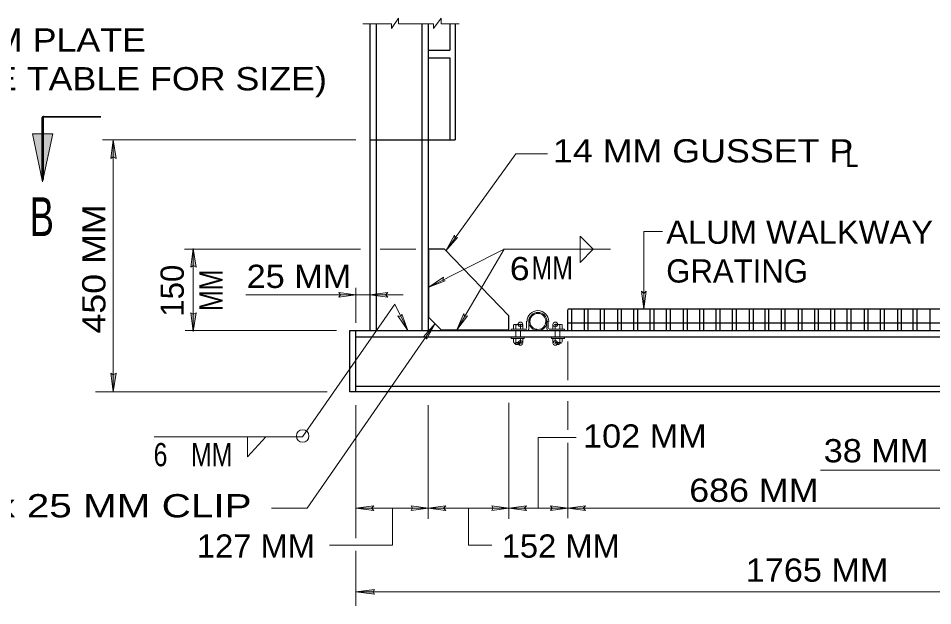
# Model space of a CAD drawing. Extents: x 312601.858 to 312602.699, y 144420.109 to 144420.704.
# Drawn here: x 312601.9235 to 312602.0414, y 144420.4587 to 144420.5345 of the extents above; entities that cross this region are included whole.
import ezdxf
from ezdxf.enums import TextEntityAlignment as Align

# ---------------------------------------------------------------- set-up
doc = ezdxf.new("R2010")
doc.units = 0
doc.header["$LTSCALE"] = 0.0012
doc.header["$PDMODE"] = 32
doc.header["$PDSIZE"] = 0.0006
doc.linetypes.add('LONG_DASHED', pattern=[7.5, 6, -1.5])
for name, color, linetype, lineweight in [('1', 7, 'Continuous', 13), ('2', 7, 'Continuous', 13), ('3', 7, 'Continuous', 13), ('39', 7, 'Continuous', 13), ('5', 7, 'Continuous', 25)]:
    doc.layers.add(name, color=color, linetype=linetype, lineweight=lineweight)

msp = doc.modelspace()

# ---------------------------------------------------------------- hatches: boundary and pattern name
at = {"layer": '1'}
for points in [[(312601.9253, 144420.5196), (312601.9266, 144420.5196), (312601.9266, 144420.5134)], [(312601.9253, 144420.5196), (312601.9266, 144420.5196), (312601.9266, 144420.5134)], [(312601.9279, 144420.5196), (312601.9266, 144420.5196), (312601.9266, 144420.5134)], [(312601.9279, 144420.5196), (312601.9266, 144420.5196), (312601.9266, 144420.5134)]]:
    msp.add_hatch(color=256, dxfattribs=at).paths.add_polyline_path(points)
at = {"layer": '39'}
for points in [[(312601.9357, 144420.5166), (312601.9354, 144420.5164), (312601.9357, 144420.5188), (312601.9361, 144420.5164)], [(312601.946, 144420.5026), (312601.9457, 144420.5024), (312601.946, 144420.5048), (312601.9464, 144420.5024)], [(312601.946, 144420.4963), (312601.9464, 144420.4965), (312601.946, 144420.4941), (312601.9457, 144420.4965)], [(312601.9357, 144420.4885), (312601.9361, 144420.4887), (312601.9357, 144420.4863), (312601.9354, 144420.4887)], [(312601.9692, 144420.4605), (312601.9694, 144420.4602), (312601.967, 144420.4605), (312601.9694, 144420.4608)], [(312601.9692, 144420.4605), (312601.9694, 144420.4602), (312601.967, 144420.4605), (312601.9694, 144420.4608)]]:
    msp.add_hatch(color=256, dxfattribs=at).paths.add_polyline_path(points)

# ---------------------------------------------------------------- linework, layer by layer
at = {"layer": '1'}
for p, q in [((312601.9679, 144420.5338), (312601.9716, 144420.5338)), ((312601.9716, 144420.5332), (312601.9725, 144420.5345)), ((312601.9716, 144420.5332), (312601.9716, 144420.5338)), ((312601.9725, 144420.5338), (312601.9725, 144420.5345)), ((312601.9725, 144420.5338), (312601.977, 144420.5338)), ((312601.977, 144420.5332), (312601.978, 144420.5345)), ((312601.977, 144420.5332), (312601.977, 144420.5338)), ((312601.978, 144420.5338), (312601.978, 144420.5345)), ((312601.978, 144420.5338), (312601.9803, 144420.5338)), ((312601.9265, 144420.5137), (312601.9265, 144420.5217)), ((312601.9343, 144420.5188), (312601.967, 144420.5188)), ((312601.9357, 144420.5188), (312601.9357, 144420.4863)), ((312602.0041, 144420.497), (312602.0041, 144420.507)), ((312602.0041, 144420.507), (312602.0065, 144420.507)), ((312601.9959, 144420.5064), (312601.9976, 144420.5047)), ((312601.9676, 144420.5047), (312601.9449, 144420.5047)), ((312601.946, 144420.5047), (312601.946, 144420.4942)), ((312601.9747, 144420.5047), (312601.9701, 144420.5047)), ((312601.9764, 144420.4998), (312601.9861, 144420.5047)), ((312601.9764, 144420.5047), (312601.9764, 144420.4959)), ((312601.98, 144420.4943), (312601.9861, 144420.5047)), ((312601.986, 144420.5047), (312601.9998, 144420.5047)), ((312601.9959, 144420.503), (312601.9976, 144420.5047)), ((312601.967, 144420.4952), (312601.967, 144420.4997)), ((312601.967, 144420.4988), (312601.9528, 144420.4988)), ((312601.9607, 144420.4713), (312601.9772, 144420.4951)), ((312601.945, 144420.4942), (312601.9645, 144420.4942)), ((312601.978, 144420.4943), (312601.9867, 144420.4943)), ((312601.9943, 144420.4878), (312601.9943, 144420.4928)), ((312601.9633, 144420.4863), (312601.9334, 144420.4863)), ((312601.967, 144420.4674), (312601.967, 144420.4846)), ((312601.9763, 144420.4846), (312601.9763, 144420.4699)), ((312601.9867, 144420.4699), (312601.9867, 144420.4849)), ((312601.9943, 144420.4814), (312601.9943, 144420.4851)), ((312601.941, 144420.4805), (312601.9601, 144420.4805)), ((312601.953, 144420.4804), (312601.953, 144420.4779)), ((312601.9943, 144420.47), (312601.9943, 144420.4797)), ((312601.9607, 144420.4713), (312601.9561, 144420.4713)), ((312601.967, 144420.4713), (312601.9763, 144420.4713)), ((312601.9763, 144420.4713), (312601.9867, 144420.4713)), ((312601.9867, 144420.4713), (312601.9943, 144420.4713)), ((312601.9943, 144420.4713), (312602.0436, 144420.4713)), ((312601.967, 144420.4587), (312601.967, 144420.4658)), ((312601.967, 144420.4605), (312602.0921, 144420.4605))]:
    msp.add_line(p, q, dxfattribs=at)
at = {"layer": '1', "lineweight": 25}
for p, q in [((312601.9688, 144420.5338), (312601.9688, 144420.4942)), ((312601.9696, 144420.5338), (312601.9696, 144420.4942)), ((312601.9755, 144420.5338), (312601.9755, 144420.4942)), ((312601.9763, 144420.5338), (312601.9763, 144420.4942)), ((312601.9791, 144420.5338), (312601.9791, 144420.5304)), ((312601.9798, 144420.5338), (312601.9798, 144420.5188)), ((312601.9763, 144420.5304), (312601.9791, 144420.5304)), ((312601.9763, 144420.5294), (312601.9791, 144420.5294)), ((312601.9791, 144420.5294), (312601.9791, 144420.5188)), ((312601.9688, 144420.5188), (312601.9798, 144420.5188)), ((312601.9784, 144420.5047), (312601.9764, 144420.5047)), ((312601.9784, 144420.5047), (312601.9867, 144420.4961)), ((312601.9764, 144420.4959), (312601.978, 144420.4943)), ((312601.9867, 144420.4943), (312601.9867, 144420.4961)), ((312601.9943, 144420.497), (312602.0436, 144420.497)), ((312601.9943, 144420.4942), (312601.9943, 144420.4969)), ((312601.9948, 144420.497), (312601.9948, 144420.4942)), ((312601.9964, 144420.497), (312601.9964, 144420.4942)), ((312601.9969, 144420.497), (312601.9969, 144420.4942)), ((312601.9985, 144420.497), (312601.9985, 144420.4942)), ((312601.999, 144420.497), (312601.999, 144420.4942)), ((312602.0007, 144420.497), (312602.0007, 144420.4942)), ((312602.0012, 144420.497), (312602.0012, 144420.4942)), ((312602.0028, 144420.497), (312602.0028, 144420.4942)), ((312602.0033, 144420.497), (312602.0033, 144420.4942)), ((312602.0049, 144420.497), (312602.0049, 144420.4942)), ((312602.0054, 144420.497), (312602.0054, 144420.4942)), ((312602.007, 144420.497), (312602.007, 144420.4942)), ((312602.0075, 144420.497), (312602.0075, 144420.4942)), ((312602.0092, 144420.497), (312602.0092, 144420.4942)), ((312602.0097, 144420.497), (312602.0097, 144420.4942)), ((312602.0113, 144420.497), (312602.0113, 144420.4942)), ((312602.0118, 144420.497), (312602.0118, 144420.4942)), ((312602.0134, 144420.497), (312602.0134, 144420.4942)), ((312602.0139, 144420.497), (312602.0139, 144420.4942)), ((312602.0155, 144420.497), (312602.0155, 144420.4942)), ((312602.016, 144420.497), (312602.016, 144420.4942)), ((312602.0177, 144420.497), (312602.0177, 144420.4942)), ((312602.0182, 144420.497), (312602.0182, 144420.4942)), ((312602.0197, 144420.497), (312602.0197, 144420.4942)), ((312602.0202, 144420.497), (312602.0202, 144420.4942)), ((312602.0218, 144420.497), (312602.0218, 144420.4942)), ((312602.0223, 144420.497), (312602.0223, 144420.4942)), ((312602.024, 144420.497), (312602.024, 144420.4942)), ((312602.0245, 144420.497), (312602.0245, 144420.4942)), ((312602.0261, 144420.497), (312602.0261, 144420.4942)), ((312602.0266, 144420.497), (312602.0266, 144420.4942)), ((312602.0282, 144420.497), (312602.0282, 144420.4942)), ((312602.0287, 144420.497), (312602.0287, 144420.4942)), ((312602.0303, 144420.497), (312602.0303, 144420.4942)), ((312602.0308, 144420.497), (312602.0308, 144420.4942)), ((312602.0325, 144420.497), (312602.0325, 144420.4942)), ((312602.033, 144420.497), (312602.033, 144420.4942)), ((312602.0346, 144420.497), (312602.0346, 144420.4942)), ((312602.0351, 144420.497), (312602.0351, 144420.4942)), ((312602.0368, 144420.497), (312602.0368, 144420.4942)), ((312602.0373, 144420.497), (312602.0373, 144420.4942)), ((312602.0388, 144420.497), (312602.0388, 144420.4942)), ((312602.0393, 144420.497), (312602.0393, 144420.4942)), ((312602.041, 144420.497), (312602.041, 144420.4942)), ((312601.9943, 144420.4952), (312602.0436, 144420.4952)), ((312601.9662, 144420.4863), (312601.9662, 144420.4942)), ((312601.9662, 144420.4942), (312601.9917, 144420.4942)), ((312601.967, 144420.4863), (312601.967, 144420.4942)), ((312601.9917, 144420.4942), (312602.0929, 144420.4942)), ((312601.967, 144420.4934), (312602.0921, 144420.4934)), ((312602.0921, 144420.487), (312601.967, 144420.487)), ((312602.0929, 144420.4863), (312601.9662, 144420.4863))]:
    msp.add_line(p, q, dxfattribs=at)
at = {"layer": '1'}
for points in [[(312601.9267, 144420.5219), (312601.9267, 144420.5137), (312601.9265, 144420.5217)], [(312601.9786, 144420.5045), (312601.9876, 144420.517), (312601.9917, 144420.517)], [(312601.9731, 144420.4988), (312601.9688, 144420.4988), (312601.967, 144420.4988)], [(312601.9601, 144420.4805), (312601.972, 144420.4976), (312601.9737, 144420.4942)], [(312602.0269, 144420.4762), (312602.0436, 144420.4762), (312602.0458, 144420.4762), (312602.0511, 144420.4762)]]:
    msp.add_lwpolyline(points, dxfattribs=at)
at = {"layer": '1', "lineweight": 35}
msp.add_lwpolyline([(312601.9266, 144420.5196), (312601.9266, 144420.5218), (312601.9341, 144420.5218)], dxfattribs=at)
msp.add_lwpolyline([(312601.9266, 144420.5196), (312601.9266, 144420.5218), (312601.9341, 144420.5218)], dxfattribs=at)
at = {"layer": '1'}
for points in [[(312601.9253, 144420.5196), (312601.9266, 144420.5196), (312601.9266, 144420.5134)], [(312601.9253, 144420.5196), (312601.9266, 144420.5196), (312601.9266, 144420.5134)], [(312601.9279, 144420.5196), (312601.9266, 144420.5196), (312601.9266, 144420.5134)], [(312601.9279, 144420.5196), (312601.9266, 144420.5196), (312601.9266, 144420.5134)], [(312601.9801, 144420.5062), (312601.9786, 144420.5045), (312601.9797, 144420.5065), (312601.9798, 144420.5061)], [(312601.9785, 144420.5006), (312601.9764, 144420.4998), (312601.9783, 144420.5011), (312601.9782, 144420.5007)], [(312601.9648, 144420.4991), (312601.967, 144420.4988), (312601.9648, 144420.4985), (312601.965, 144420.4988)], [(312601.9711, 144420.4985), (312601.9688, 144420.4988), (312601.9711, 144420.4991), (312601.9708, 144420.4988)], [(312602.0044, 144420.4993), (312602.0041, 144420.497), (312602.0038, 144420.4993), (312602.0041, 144420.499)], [(312601.9729, 144420.4963), (312601.9737, 144420.4942), (312601.9724, 144420.4961), (312601.9728, 144420.496)], [(312601.9814, 144420.4961), (312601.98, 144420.4943), (312601.9809, 144420.4964), (312601.981, 144420.496)], [(312601.9757, 144420.4934), (312601.9772, 144420.4951), (312601.9761, 144420.4931), (312601.976, 144420.4934)], [(312601.9693, 144420.471), (312601.967, 144420.4713), (312601.9693, 144420.4716), (312601.969, 144420.4713)], [(312601.9741, 144420.4716), (312601.9763, 144420.4713), (312601.9741, 144420.471), (312601.9743, 144420.4713)], [(312601.9786, 144420.471), (312601.9763, 144420.4713), (312601.9786, 144420.4716), (312601.9783, 144420.4713)], [(312601.9845, 144420.4716), (312601.9867, 144420.4713), (312601.9845, 144420.471), (312601.9847, 144420.4713)], [(312601.989, 144420.471), (312601.9867, 144420.4713), (312601.989, 144420.4716), (312601.9887, 144420.4713)], [(312601.9921, 144420.4716), (312601.9943, 144420.4713), (312601.9921, 144420.471), (312601.9923, 144420.4713)], [(312601.9966, 144420.471), (312601.9943, 144420.4713), (312601.9966, 144420.4716), (312601.9963, 144420.4713)]]:
    msp.add_lwpolyline(points, close=True, dxfattribs=at)
msp.add_circle((312601.960125, 144420.4806), 0.000806, dxfattribs=at)
at = {"layer": '2'}
for p, q in [((312601.9905, 144420.4804), (312601.9905, 144420.4713)), ((312601.9905, 144420.4804), (312601.9954, 144420.4804)), ((312601.9717, 144420.4713), (312601.9717, 144420.4665)), ((312601.9636, 144420.4665), (312601.9717, 144420.4665))]:
    msp.add_line(p, q, dxfattribs=at)
for points in [[(312601.9959, 144420.503), (312601.9959, 144420.5047), (312601.9959, 144420.5064)], [(312601.9815, 144420.4713), (312601.9815, 144420.4665), (312601.9845, 144420.4665)]]:
    msp.add_lwpolyline(points, dxfattribs=at)
at = {"layer": '3'}
for p, q in [((312601.9893, 144420.4955), (312601.9898, 144420.4963)), ((312601.9899, 144420.4962), (312601.99, 144420.4965)), ((312601.9873, 144420.495), (312601.9873, 144420.4944)), ((312601.9884, 144420.495), (312601.9874, 144420.495)), ((312601.9876, 144420.495), (312601.9876, 144420.4944)), ((312601.9882, 144420.495), (312601.9882, 144420.4944)), ((312601.9885, 144420.4949), (312601.9885, 144420.4944)), ((312601.9893, 144420.4954), (312601.9893, 144420.4944)), ((312601.9893, 144420.4952), (312601.9894, 144420.4954)), ((312601.9914, 144420.4951), (312601.9916, 144420.4954)), ((312601.9915, 144420.4954), (312601.9916, 144420.4956)), ((312601.9916, 144420.4954), (312601.9916, 144420.4944)), ((312601.9924, 144420.495), (312601.9924, 144420.4944)), ((312601.9926, 144420.495), (312601.9935, 144420.495)), ((312601.9927, 144420.495), (312601.9927, 144420.4944)), ((312601.9933, 144420.495), (312601.9933, 144420.4944)), ((312601.9936, 144420.4949), (312601.9936, 144420.4944)), ((312601.987, 144420.4944), (312601.989, 144420.4944)), ((312601.987, 144420.4942), (312601.987, 144420.4944)), ((312601.9873, 144420.4944), (312601.9879, 144420.4944)), ((312601.9885, 144420.4944), (312601.9879, 144420.4944)), ((312601.9882, 144420.4942), (312601.9891, 144420.4942)), ((312601.9891, 144420.4942), (312601.9955, 144420.4942)), ((312601.9908, 144420.4942), (312601.9909, 144420.4944)), ((312601.991, 144420.4943), (312601.9912, 144420.4946)), ((312601.9939, 144420.4944), (312601.9919, 144420.4944)), ((312601.9924, 144420.4944), (312601.993, 144420.4944)), ((312601.9933, 144420.4942), (312601.9927, 144420.4942)), ((312601.9936, 144420.4944), (312601.993, 144420.4944)), ((312601.9939, 144420.4942), (312601.9939, 144420.4944)), ((312601.987, 144420.4932), (312601.987, 144420.4934)), ((312601.9873, 144420.4927), (312601.9873, 144420.4932)), ((312601.9873, 144420.4932), (312601.9879, 144420.4932)), ((312601.9876, 144420.4927), (312601.9876, 144420.4932)), ((312601.9876, 144420.4924), (312601.9881, 144420.4924)), ((312601.9885, 144420.4932), (312601.9879, 144420.4932)), ((312601.9881, 144420.4926), (312601.9881, 144420.4924)), ((312601.9882, 144420.4927), (312601.9882, 144420.4932)), ((312601.9885, 144420.4927), (312601.9885, 144420.4932)), ((312601.9922, 144420.4932), (312601.9922, 144420.4934)), ((312601.9939, 144420.4932), (312601.9922, 144420.4932)), ((312601.9924, 144420.4927), (312601.9924, 144420.4932)), ((312601.9924, 144420.4932), (312601.993, 144420.4932)), ((312601.9926, 144420.4926), (312601.9935, 144420.4926)), ((312601.9927, 144420.4927), (312601.9927, 144420.4932)), ((312601.9932, 144420.4924), (312601.9928, 144420.4924)), ((312601.9936, 144420.4932), (312601.993, 144420.4932)), ((312601.9933, 144420.4927), (312601.9933, 144420.4932)), ((312601.9936, 144420.4927), (312601.9936, 144420.4932)), ((312601.9939, 144420.4932), (312601.9939, 144420.4934))]:
    msp.add_line(p, q, dxfattribs=at)
at = {"layer": '3', "linetype": 'LONG_DASHED'}
for p, q in [((312601.9876, 144420.4942), (312601.9876, 144420.4935)), ((312601.9882, 144420.4942), (312601.9882, 144420.4935)), ((312601.9927, 144420.4942), (312601.9927, 144420.4935)), ((312601.9933, 144420.4942), (312601.9933, 144420.4935))]:
    msp.add_line(p, q, dxfattribs=at)
at = {"layer": '3'}
for points in [[(312601.9906, 144420.4964), (312601.9906, 144420.4965), (312601.9908, 144420.4965)], [(312601.9912, 144420.4962), (312601.9912, 144420.4963), (312601.9913, 144420.4962)], [(312601.989, 144420.4954), (312601.989, 144420.4952), (312601.989, 144420.4945)], [(312601.9896, 144420.4945), (312601.9897, 144420.4947), (312601.9896, 144420.4948)], [(312601.9918, 144420.4954), (312601.9918, 144420.4952), (312601.9918, 144420.4945)], [(312601.9855, 144420.4942), (312601.9876, 144420.4942), (312601.9882, 144420.4942)], [(312601.9902, 144420.4942), (312601.9903, 144420.4944), (312601.9901, 144420.4944)], [(312601.9928, 144420.4942), (312601.9918, 144420.4942), (312601.9915, 144420.4942)], [(312601.987, 144420.4932), (312601.9887, 144420.4932), (312601.9887, 144420.4934)], [(312601.9884, 144420.4926), (312601.9874, 144420.4926), (312601.9876, 144420.4924)], [(312601.9932, 144420.4926), (312601.9932, 144420.4924), (312601.9928, 144420.4924)]]:
    msp.add_lwpolyline(points, dxfattribs=at)
for radius in [0.001175, 0.00103]:
    msp.add_circle((312601.990455, 144420.495376), radius, dxfattribs=at)
for centre, radius, start, end in [((312601.990455, 144420.495376), 0.001399, 0, 180), ((312601.988977, 144420.494465), 0.0000792, 270, 0), ((312601.989082, 144420.494399), 0.000198, 270, 0), ((312601.991828, 144420.494399), 0.000198, 180, 270), ((312601.991934, 144420.494465), 0.0000792, 180, 270)]:
    msp.add_arc(centre, radius, start, end, dxfattribs=at)
for centre, major_axis, start_param, end_param in [((312601.987428, 144420.494751), (0.000267, 0), 0.970898, 2.1858445), ((312601.987893, 144420.494071), (0.001082, 0), 1.2763403, 1.8649531), ((312601.987882, 144420.493695), (-0.001534, 0), 4.4986502, 4.498801), ((312601.988358, 144420.494751), (0.000267, 0), 0.9448732, 2.1695573), ((312601.988835, 144420.493695), (0.001534, 0), 1.7843843, 1.7845351), ((312601.992076, 144420.493695), (-0.001534, 0), 4.4986502, 4.5023266), ((312601.992552, 144420.494751), (-0.000267, 0), 4.113628, 5.3383121), ((312601.993017, 144420.494071), (-0.001082, 0), 4.4182323, 5.006845), ((312601.993029, 144420.493695), (0.001534, 0), 1.7843843, 1.7845351), ((312601.993482, 144420.494751), (-0.000267, 0), 4.0973408, 5.3122873), ((312601.987428, 144420.492882), (0.000267, 0), 4.0973408, 5.3122873), ((312601.987893, 144420.493561), (0.001082, 0), 4.4182323, 5.006845), ((312601.988358, 144420.492882), (0.000267, 0), 4.113628, 5.3383121), ((312601.987882, 144420.493938), (-0.001534, 0), 1.7843843, 1.7845351), ((312601.992552, 144420.492882), (-0.000267, 0), 0.9448732, 2.1695573), ((312601.993017, 144420.493561), (-0.001082, 0), 1.2763403, 1.8649531), ((312601.993482, 144420.492882), (-0.000267, 0), 0.970898, 2.1858445)]:
    msp.add_ellipse(centre, major_axis=major_axis, ratio=0.83375, start_param=start_param, end_param=end_param, dxfattribs=at)
for p in [(312601.9882, 144420.495), (312601.9927, 144420.495), (312601.9882, 144420.4926), (312601.9927, 144420.4926)]:
    msp.add_point(p, dxfattribs=at)
at = {"layer": '39'}
for points in [[(312601.9357, 144420.5166), (312601.9354, 144420.5164), (312601.9357, 144420.5188), (312601.9361, 144420.5164)], [(312601.946, 144420.5026), (312601.9457, 144420.5024), (312601.946, 144420.5048), (312601.9464, 144420.5024)], [(312601.946, 144420.4963), (312601.9464, 144420.4965), (312601.946, 144420.4941), (312601.9457, 144420.4965)], [(312601.9357, 144420.4885), (312601.9361, 144420.4887), (312601.9357, 144420.4863), (312601.9354, 144420.4887)], [(312601.9692, 144420.4605), (312601.9694, 144420.4602), (312601.967, 144420.4605), (312601.9694, 144420.4608)], [(312601.9692, 144420.4605), (312601.9694, 144420.4602), (312601.967, 144420.4605), (312601.9694, 144420.4608)]]:
    msp.add_lwpolyline(points, close=True, dxfattribs=at)
at = {"layer": '5', "lineweight": 13}
msp.add_line((312601.953, 144420.4779), (312601.9554, 144420.4805), dxfattribs=at)

# ---------------------------------------------------------------- texts
at = {"layer": '2'}
for s, width, p in [('SHIM PLATE', 1.15, (312601.9125, 144420.5302)), ('(SEE TABLE FOR SIZE)', 1.15, (312601.9125, 144420.5252)), ('14 MM GUSSET P', 1.15, (312601.9924, 144420.5159)), ('ALUM WALKWAY', 1.05, (312602.007, 144420.5054))]:
    msp.add_text(s, height=0.003, dxfattribs=dict(at, width=width)).set_placement(p)
for s, height, width, p in [('L', 0.003, 0.75, (312602.03095, 144420.5153)), ('B', 0.005, 0.7, (312601.9265, 144420.5064)), ('6 ', 0.003, 1.15, (312601.98875, 144420.5007)), ('MM', 0.003, 0.8, (312601.9923, 144420.5008)), ('25 MM', 0.003, 1.1, (312601.95965, 144420.4997)), ('102 MM', 0.003, 1.1, (312602.00425, 144420.4791)), ('6', 0.003, 0.8, (312601.9418, 144420.4767)), ('MM', 0.003, 0.8, (312601.9484, 144420.4767)), ('38 MM', 0.003, 1.1, (312602.03405, 144420.4772)), ('686 MM', 0.003, 1.15, (312602.0183, 144420.4721)), ('25 x 25 MM CLIP', 0.003, 1.3, (312601.9334, 144420.4701)), ('127 MM', 0.003, 1.05, (312601.9541, 144420.4649)), ('152 MM', 0.003, 1.05, (312601.9934, 144420.4649)), ('1765 MM', 0.003, 1.1, (312602.02645, 144420.4618))]:
    msp.add_text(s, height=height, dxfattribs=dict(at, width=width)).set_placement(p, align=Align.CENTER)
for s, width, p in [('450 MM', 1.15, (312601.9347, 144420.50215)), ('MM', 0.8, (312601.9498, 144420.4994))]:
    msp.add_text(s, height=0.003, rotation=90, dxfattribs=dict(at, width=width)).set_placement(p, align=Align.CENTER)
msp.add_text('GRATING', height=0.003, dxfattribs=at).set_placement((312602.007, 144420.5004))
msp.add_text('150', height=0.003, rotation=90, dxfattribs=at).set_placement((312601.9448, 144420.49935), align=Align.CENTER)

doc.saveas('drawing.dxf')
